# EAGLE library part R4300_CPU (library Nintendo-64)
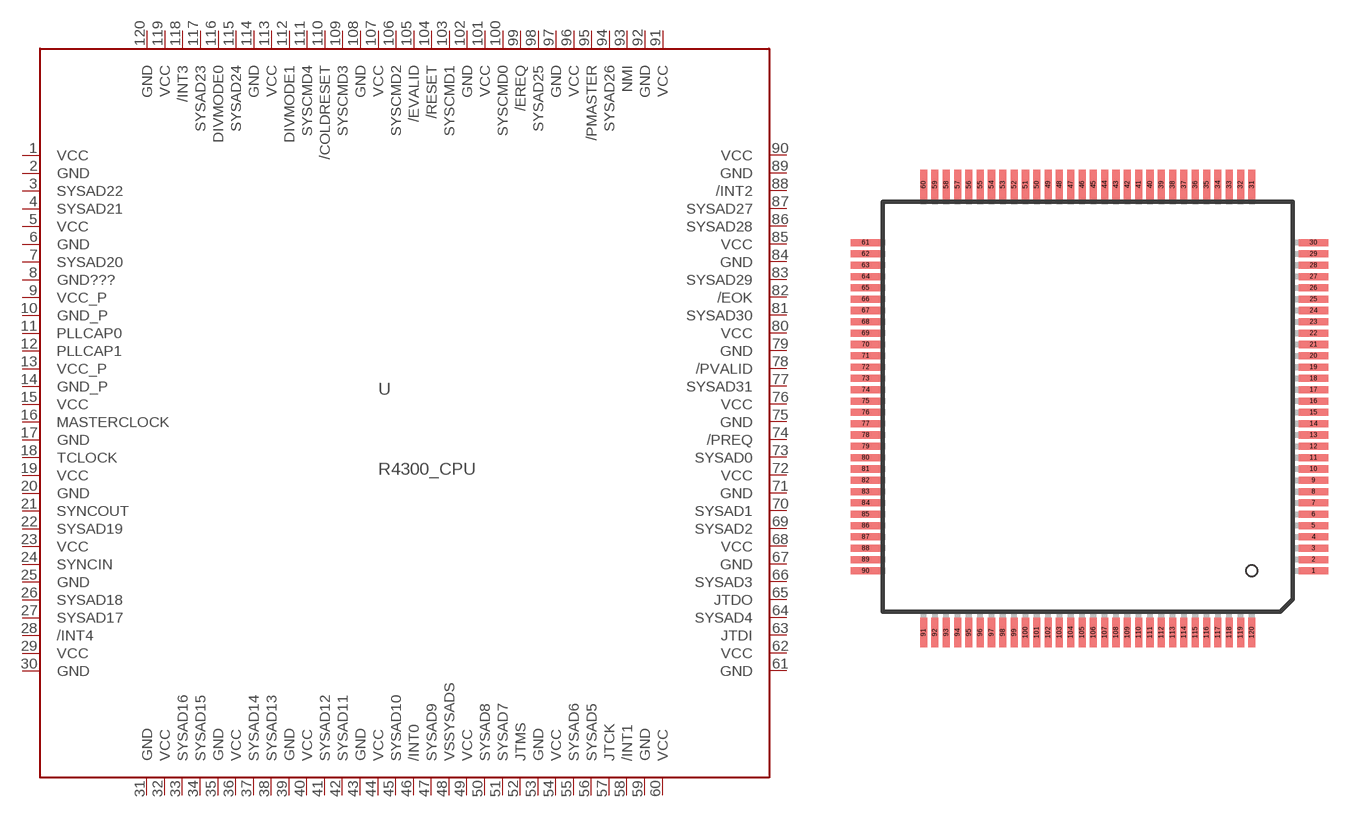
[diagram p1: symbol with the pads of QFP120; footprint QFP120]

Designator prefix -

## R4300_CPU  [QFP120]
1  VCC  pwr
2  GND  pwr
3  SYSAD22
4  SYSAD21
5  VCC  pwr
6  GND  pwr
7  SYSAD20
8  GND???  pwr
9  VCC_P  pwr
10  GND_P  pwr
11  PLLCAP0  in
12  PLLCAP1  in
13  VCC_P  pwr
14  GND_P  pwr
15  VCC  pwr
16  MASTERCLOCK  in
17  GND  pwr
18  TCLOCK
19  VCC  pwr
20  GND  pwr
21  SYNCOUT
22  SYSAD19
23  VCC  pwr
24  SYNCIN  in
25  GND  pwr
26  SYSAD18
27  SYSAD17
28  /INT4  in
29  VCC  pwr
30  GND  pwr
31  GND  pwr
32  VCC  pwr
33  SYSAD16
34  SYSAD15
35  GND  pwr
36  VCC  pwr
37  SYSAD14
38  SYSAD13
39  GND  pwr
40  VCC  pwr
41  SYSAD12
42  SYSAD11
43  GND  pwr
44  VCC  pwr
45  SYSAD10
46  /INT0  in
47  SYSAD9
48  VSSYSADS
49  VCC  pwr
50  SYSAD8
51  SYSAD7
52  JTMS  in
53  GND  pwr
54  VCC  pwr
55  SYSAD6
56  SYSAD5
57  JTCK  in
58  /INT1  in
59  GND  pwr
60  VCC  pwr
61  GND  pwr
62  VCC  pwr
63  JTDI  in
64  SYSAD4
65  JTDO  out
66  SYSAD3
67  GND  pwr
68  VCC  pwr
69  SYSAD2
70  SYSAD1
71  GND  pwr
72  VCC  pwr
73  SYSAD0
74  /PREQ  out
75  GND  pwr
76  VCC  pwr
77  SYSAD31
78  /PVALID  out
79  GND  pwr
80  VCC  pwr
81  SYSAD30
82  /EOK  in
83  SYSAD29
84  GND  pwr
85  VCC  pwr
86  SYSAD28
87  SYSAD27
88  /INT2  in
89  GND  pwr
90  VCC  pwr
91  VCC  pwr
92  GND  pwr
93  NMI  in
94  SYSAD26
95  /PMASTER  out
96  VCC  pwr
97  GND  pwr
98  SYSAD25
99  /EREQ  in
100  SYSCMD0
101  VCC  pwr
102  GND  pwr
103  SYSCMD1
104  /RESET  in
105  /EVALID  in
106  SYSCMD2
107  VCC  pwr
108  GND  pwr
109  SYSCMD3
110  /COLDRESET  in
111  SYSCMD4
112  DIVMODE1  in
113  VCC  pwr
114  GND  pwr
115  SYSAD24
116  DIVMODE0  in
117  SYSAD23
118  /INT3  in
119  VCC  pwr
120  GND  pwr

## Footprint QFP120 (pad centres in mm)
smd 2.1 x 0.5: 1 15.95,-11.6; 2 15.95,-10.8; 3 15.95,-10; 4 15.95,-9.2; 5 15.95,-8.4; 6 15.95,-7.6; 7 15.95,-6.8; 8 15.95,-6; 9 15.95,-5.2; 10 15.95,-4.4; 11 15.95,-3.6; 12 15.95,-2.8; 13 15.95,-2; 14 15.95,-1.2; 15 15.95,-0.4; 16 15.95,0.4; 17 15.95,1.2; 18 15.95,2; 19 15.95,2.8; 20 15.95,3.6; 21 15.95,4.4; 22 15.95,5.2; 23 15.95,6; 24 15.95,6.8; 25 15.95,7.6; 26 15.95,8.4; 27 15.95,9.2; 28 15.95,10; 29 15.95,10.8; 30 15.95,11.6; 61 -15.7,11.6; 62 -15.7,10.8; 63 -15.7,10; 64 -15.7,9.2; 65 -15.7,8.4; 66 -15.7,7.6; 67 -15.7,6.8; 68 -15.7,6; 69 -15.7,5.2; 70 -15.7,4.4; 71 -15.7,3.6; 72 -15.7,2.8; 73 -15.7,2; 74 -15.7,1.2; 75 -15.7,0.4; 76 -15.7,-0.4; 77 -15.7,-1.2; 78 -15.7,-2; 79 -15.7,-2.8; 80 -15.7,-3.6; 81 -15.7,-4.4; 82 -15.7,-5.2; 83 -15.7,-6; 84 -15.7,-6.8; 85 -15.7,-7.6; 86 -15.7,-8.4; 87 -15.7,-9.2; 88 -15.7,-10; 89 -15.7,-10.8; 90 -15.7,-11.6
smd 0.5 x 2.1: 31 11.6,15.7; 32 10.8,15.7; 33 10,15.7; 34 9.2,15.7; 35 8.4,15.7; 36 7.6,15.7; 37 6.8,15.7; 38 6,15.7; 39 5.2,15.7; 40 4.4,15.7; 41 3.6,15.7; 42 2.8,15.7; 43 2,15.7; 44 1.2,15.7; 45 0.4,15.7; 46 -0.4,15.7; 47 -1.2,15.7; 48 -2,15.7; 49 -2.8,15.7; 50 -3.6,15.7; 51 -4.4,15.7; 52 -5.2,15.7; 53 -6,15.7; 54 -6.8,15.7; 55 -7.6,15.7; 56 -8.4,15.7; 57 -9.2,15.7; 58 -10,15.7; 59 -10.8,15.7; 60 -11.6,15.7; 91 -11.6,-15.95; 92 -10.8,-15.95; 93 -10,-15.95; 94 -9.2,-15.95; 95 -8.4,-15.95; 96 -7.6,-15.95; 97 -6.8,-15.95; 98 -6,-15.95; 99 -5.2,-15.95; 100 -4.4,-15.95; 101 -3.6,-15.95; 102 -2.8,-15.95; 103 -2,-15.95; 104 -1.2,-15.95; 105 -0.4,-15.95; 106 0.4,-15.95; 107 1.2,-15.95; 108 2,-15.95; 109 2.8,-15.95; 110 3.6,-15.95; 111 4.4,-15.95; 112 5.2,-15.95; 113 6,-15.95; 114 6.8,-15.95; 115 7.6,-15.95; 116 8.4,-15.95; 117 9.2,-15.95; 118 10,-15.95; 119 10.8,-15.95; 120 11.6,-15.95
